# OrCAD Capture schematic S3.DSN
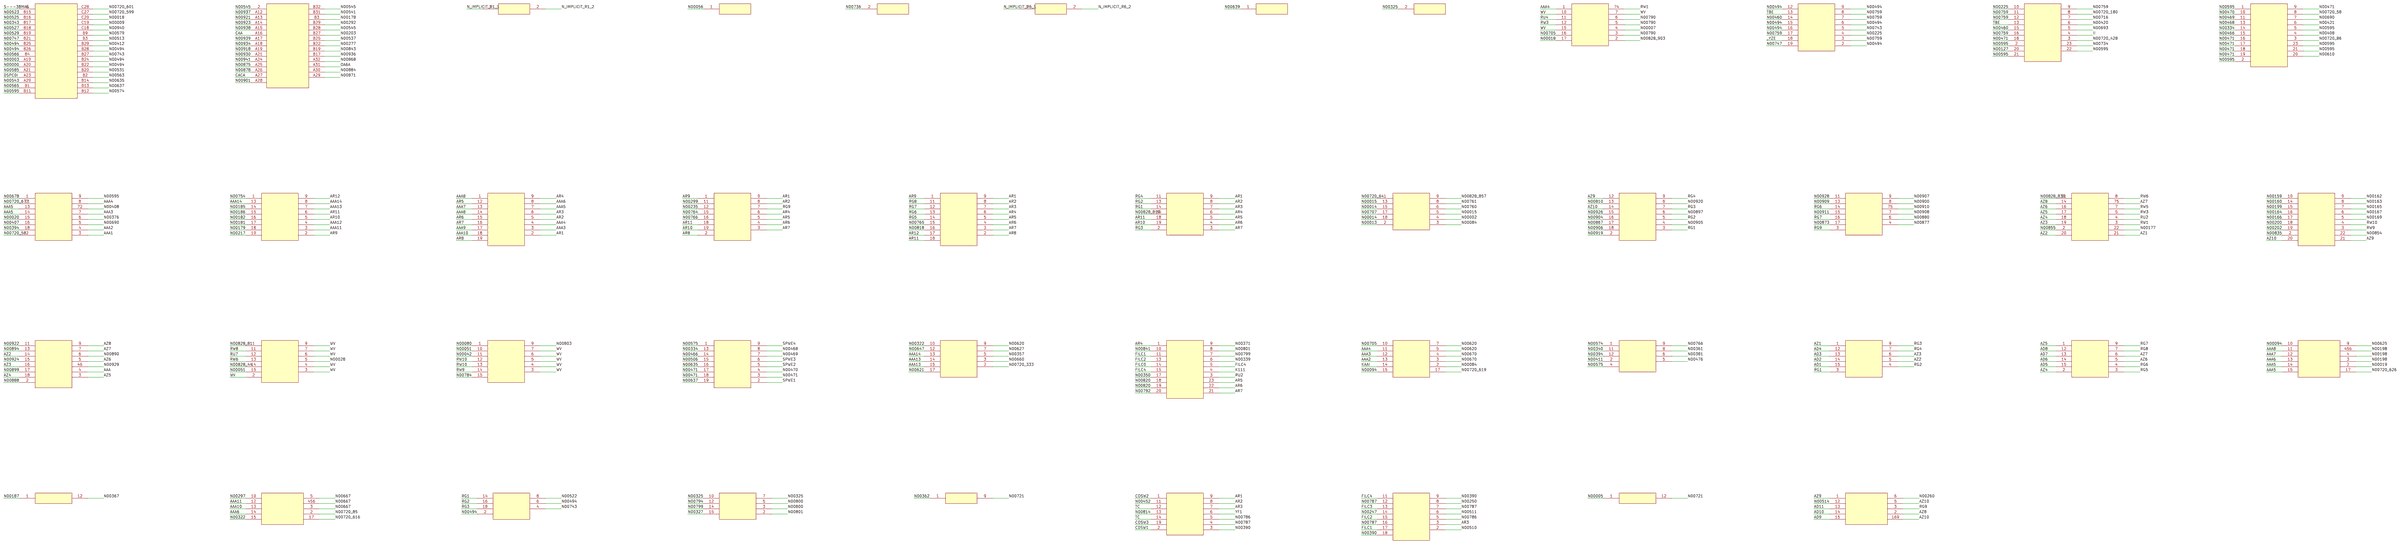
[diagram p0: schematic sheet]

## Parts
P1  CONNECTOR
P2  CONNECTOR
R1  1K00
R6  1K00
R7  1K00
R9  1K00
R12  120R
R13  120R
U1  74F244
U2  74F374
U3  74F244
U4  74F161
U6  74F161
U7  74F161
U8  74F161
U20  UNKNOWN
U21  UNKNOWN
U23  74F374
U24  74F374
U26  74F374
U27  UNKNOWN
U28  UNKNOWN
U29  UNKNOWN
U30  74F244
U31  74F244
U32  29520
U33  29520
U34  74F244
U35  74F163
U36  74F163
U38  74F374
U54  UNKNOWN
U60  74F240
U68  74LS298
U69  74LS298
U72  74F32
U83  74BCI2244
U84  74F161
U85  74F240
U86  UNKNOWN
U87  74F244
U89  74F08
U91  74LS298

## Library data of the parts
P1 = OBS_P1
P2 = OBS_P2
R1 = OBS_R1
R6 = OBS_R6
R7 = OBS_R7
R9 = OBS_R9
R12 = OBS_R12
R13 = OBS_R13
U1 = OBS_U1
U2 = OBS_U2
U3 = OBS_U3
U4 = OBS_U4
U6 = OBS_U6
U7 = OBS_U7
U8 = OBS_U8
U20 = OBS_U20
U21 = OBS_U21
U23 = OBS_U23
U24 = OBS_U24
U26 = OBS_U26
U27 = OBS_U27
U28 = OBS_U28
U29 = OBS_U29
U30 = OBS_U30
U31 = OBS_U31
U32 = OBS_U32
U33 = OBS_U33
U34 = OBS_U34
U35 = OBS_U35
U36 = OBS_U36
U38 = OBS_U38
U54 = OBS_U54
U60 = OBS_U60
U68 = OBS_U68
U69 = OBS_U69
U72 = OBS_U72
U83 = OBS_U83
U84 = OBS_U84
U85 = OBS_U85
U86 = OBS_U86
U87 = OBS_U87
U89 = OBS_U89
U91 = OBS_U91

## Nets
_YZE: U2.18
AAA: U34.4
AAA1: U23.3
AAA2: U6.13 U23.4
AAA3: U6.12 U23.7 U26.3
AAA4: U1.1 U6.11 U23.8 U26.4
AAA5: U7.14 U7.15 U23.13 U23.14 U26.7
AAA6: U7.13 U8.14 U26.8
AAA7: U7.12 U26.13
AAA8: U7.11 U26.1 U26.14
AAA9: U26.17
AAA10: U8.13 U26.18
AAA11: U8.12 U24.3
AAA12: U24.4
AAA13: U4.14 U4.15 U24.7
AAA14: U4.13 U24.8 U24.13
AD1: U68.15
AD2: U68.14
AD3: U68.13
AD4: U68.12
AD5: U69.15
AD6: U69.14
AD7: U69.13
AD8: U69.12
AD9: U91.15
AD10: U91.14
AD11: U91.13
AR1: U26.2 U27.9 U28.9 U29.9 U86.9
AR2: U26.5 U27.8 U28.8 U29.8 U86.8
AR3: U26.6 U28.7 U29.7 U86.7 U87.3
AR4: U26.9 U27.6 U28.6 U29.6 U54.1
AR5: U26.12 U27.5 U28.5 U29.5 U54.23
AR6: U26.15 U27.4 U28.4 U29.4 U54.22
AR7: U26.16 U27.3 U28.3 U29.3 U54.21
AR8: U26.19 U27.2 U28.2
AR9: U24.2 U27.1 U28.1
AR10: U24.5 U27.19 U29.19
AR11: U24.6 U27.18 U28.18 U29.18
AR12: U24.9 U28.17
AZ1: U32.21 U68.1
AZ2: U32.20 U34.14 U68.5
AZ3: U32.19 U34.16 U68.6
AZ4: U32.18 U34.18 U69.2
AZ5: U32.17 U34.3 U69.1
AZ6: U32.16 U34.5 U69.5
AZ7: U32.75 U34.7 U69.6
AZ8: U32.14 U34.9 U91.2
AZ9: U30.12 U33.21 U91.1
AZ10: U30.14 U33.20 U91.5 U91.169
CAA: P2.A16
CACA: P2.A27
CDSW1: U86.2
COSW2: U86.1
COSW3: U86.19
DSPC0I: P1.A23
FILC0: U54.14
FILC1: U54.11 U87.17
FILC2: U54.13 U87.15
FILC3: U87.13
FILC4: U54.5 U54.15 U87.11
II: U20.4
K111: U54.4
KAAI: U6.14
N00720_58: U21.8 U23.2
N00720_64: U3.1
N00720_85: U8.2
N00720_86: U21.3
N00720_180: U20.8
N00720_333: U4.2
N00720_428: U20.3
N00720_599: P1.C27
N00720_601: P1.C28
N00720_616: U8.17
N00720_619: U6.17
N00720_626: U7.17
N00720_677: U23.11
N00828_44: U35.14
N00828_81: U35.1
N00828_819: U29.16
N00828_839: U32.11
N00828_857: U3.9
N00828_903: U1.2
N_IMPLICIT_R1_1: R1.1
N_IMPLICIT_R1_2: R1.2
N_IMPLICIT_R6_1: R6.1
N_IMPLICIT_R6_2: R6.2
OA6A: P2.A31
RG1: U29.14 U30.3 U68.3 U83.14
RG2: U29.13 U30.5 U68.4 U83.16
RG3: U29.2 U30.7 U68.9 U83.18
RG4: U29.11 U30.9 U68.7
RG5: U28.14 U69.3
RG6: U28.13 U31.14 U69.4
RG7: U28.12 U31.16 U69.9
RG8: U28.11 U69.7
RG9: U27.7 U31.3 U91.3
RU2: U32.4 U54.3
RU4: U1.11
RU7: U35.12
RW1: U1.74 U32.3
RW3: U1.12 U32.5
RW5: U32.7
RW6: U32.8 U35.13
RW8: U35.11
RW9: U33.3 U36.14
RW10: U33.4 U36.12 U36.13
S---38MAG: P1.6
SPWE1: U38.2
SPWE2: U38.5
SPWE3: U38.6
SPWE4: U38.9
TBE: U2.13 U20.13
TC: U86.12 U86.14
WV: U1.7 U1.10 U1.15 U35.2 U35.3 U35.4 U35.6 U35.7 U35.9 U36.3 U36.4 U36.5 U36.6 U36.7
YF1: U86.6
N00014: U3.15 U3.18
N00015: U3.5 U3.13
N00018: P1.C20 U1.17
N00051: U35.15 U36.10
N00084: U3.3 U6.2
N00094: U6.15 U7.10
N00198: U7.3 U7.4 U7.456
N00225: U2.4 U20.10
N00322: U4.10 U8.15
N00325: R9.2 U84.7 U84.10
N00334: U21.14 U38.13
N00390: U86.3 U87.9 U87.18
N00394: U23.18 U60.12
N00408: U21.4 U23.72
N00460: U2.14 U20.15
N00466: U21.15 U38.14
N00468: U21.13 U38.8
N00469: U21.11 U38.7
N00470: U21.10 U38.4
N00471: U20.18 U21.9 U21.16 U21.17 U21.18 U21.19 U38.3 U38.17 U38.18
N00494: P1.825 P1.826 P1.B22 P1.B24 P1.B28 U2.2 U2.6 U2.9 U2.12 U2.15 U2.16 U83.2 U83.6
N00545: P2.2 P2.B28 P2.B32
N00574: P1.B12 U60.1
N00575: U38.1 U60.4
N00595: P1.B11 U20.2 U20.21 U20.22 U21.1 U21.2 U21.5 U21.21 U21.23 U23.9
N00620: U4.9 U6.5 U6.7
N00635: P1.B14 U38.16
N00637: P1.B13 U38.19
N00667: U8.3 U8.5 U8.456
N00670: U6.3 U6.4
N00690: U21.7 U23.5
N00705: U1.16 U6.10
N00721: U85.9 U89.12
N00743: P1.B27 U2.5 U83.4
N00747: P1.821 U2.19
N00759: U2.3 U2.7 U2.8 U2.17 U20.9 U20.11 U20.12 U20.16
N00766: U27.16 U60.9
N00786: U86.5 U87.5
N00787: U86.4 U87.7 U87.12 U87.16
N00790: U1.3 U1.5 U1.6
N00799: U54.7 U84.14
N00800: U84.3 U84.5
N00801: U54.8 U84.2
N00820: U54.18 U54.19

Not connected (* = marked no-connect by the designer): P1 84 815 816 817 818 819 A19 A20 A21 A29 B1 B2 B3 B9 B20 B29 C18 C19; P2 A12 A13 A14 A15 A17 A18 A19 A21 A24 A25 A26 A28 A29 A30 A32 B3 B17 B19 B22 B25 B27 B29 B31; R7 1; R12 1; R13 2; U1 4; U3 2 4 6 8 17; U4 3 5 7 12 17; U7 2 9; U8 10; U20 5 6 7 20 23; U21 6 20; U23 1 6 15 16; U24 1 14 15 16 17 18 19; U27 11 12 15; U28 15 16; U30 2 4 6 8 13 15 16 17 18; U31 4 6 7 8 9 11 13 15 17 75; U32 2 22; U33 2 5 6 7 8 9 10 14 15 16 17 18 19 22; U34 2 6 11 13 15 17 46; U35 5; U36 1 9 11 15; U38 15; U54 6 9 10 17 20; U60 2 5 6 8 11; U72 1 12; U83 8; U84 12 15; U85 1; U86 11 13; U87 2 6 8 14; U89 1; U91 6 12
